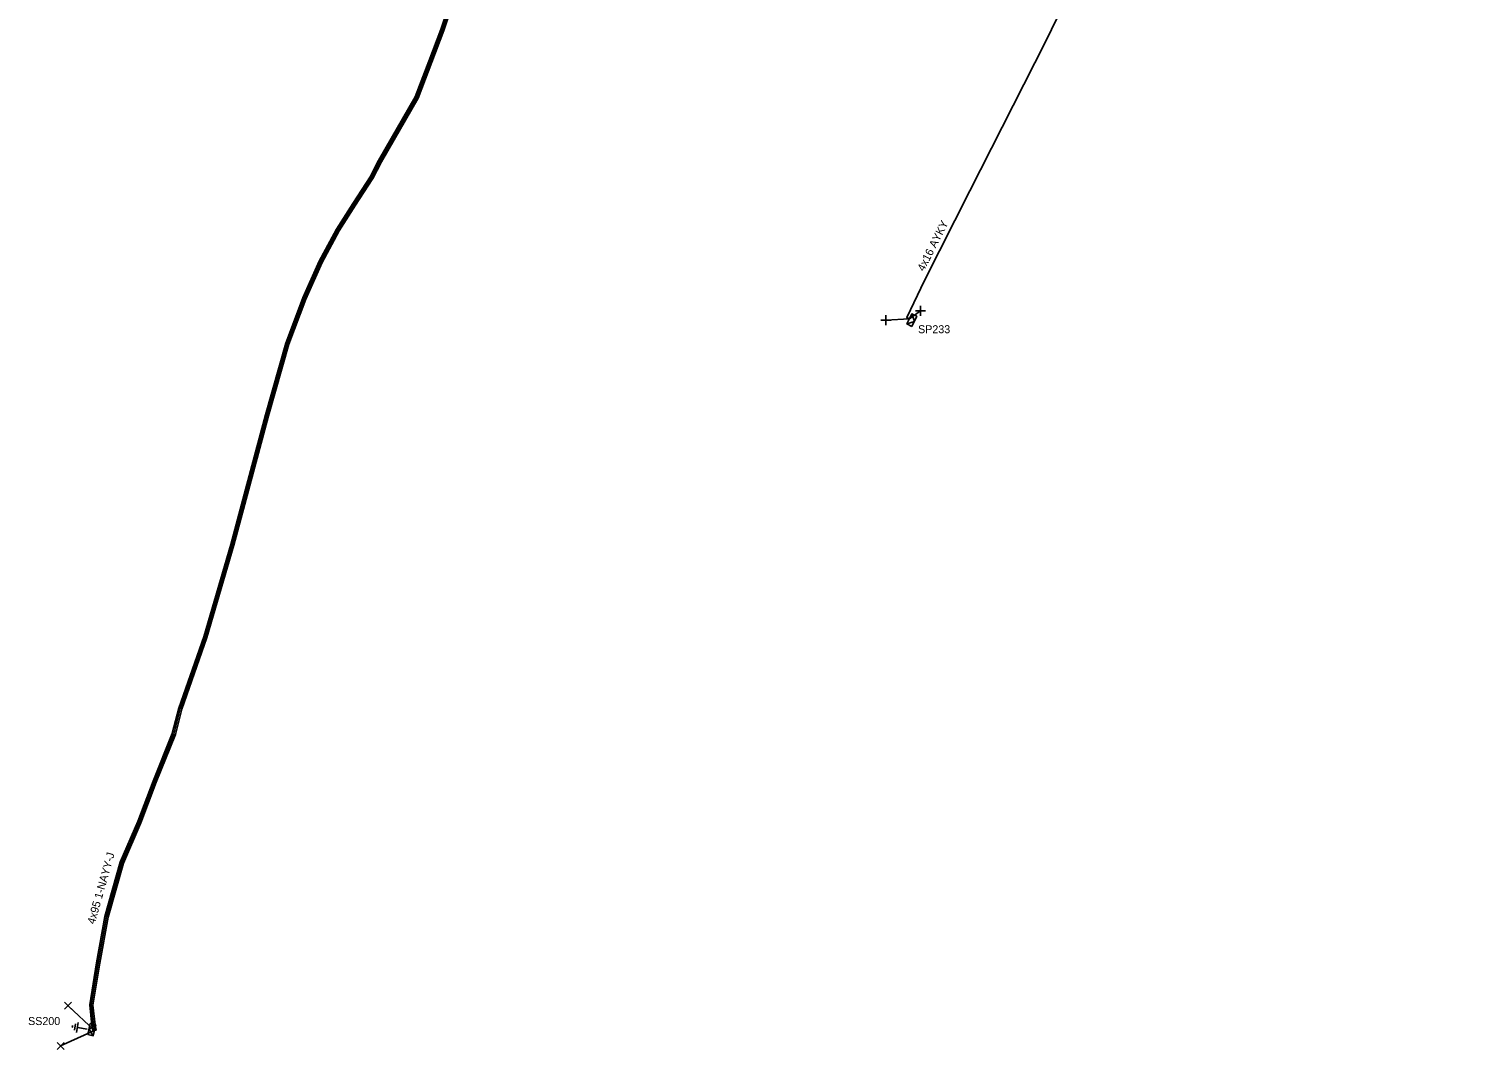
# Model space of a CAD drawing. Extents: x -788458 to -786145, y -1154772 to -1152372.
# Drawn here: x -787453 to -787274.4, y -1153371.6 to -1153244.1 of the extents above; entities that cross this region are included whole.
import ezdxf

# ---------------------------------------------------------------- set-up
doc = ezdxf.new("R2010")
doc.units = 0
for name, color, linetype in [('Vrstva 1', 7, 'Continuous'), ('Vrstva 14', 7, 'Continuous'), ('Vrstva 15', 7, 'Continuous'), ('Vrstva 20', 7, 'Continuous'), ('Vrstva 31', 7, 'Continuous'), ('Vrstva 33', 7, 'Continuous'), ('Vrstva 34', 7, 'Continuous'), ('Vrstva 5', 7, 'Continuous'), ('Vrstva 52', 7, 'Continuous'), ('Vrstva 54', 7, 'Continuous'), ('Vrstva 59', 7, 'Continuous'), ('Vrstva 6', 7, 'Continuous'), ('Vrstva 9', 7, 'Continuous')]:
    doc.layers.add(name, color=color, linetype=linetype)

# ---------------------------------------------------------------- blocks, each defined once
blk = doc.blocks.new('NN800')
at = {"layer": 'Vrstva 1'}
for points in [[(-0.44, 0.44), (0.44, -0.44)], [(-0.44, -0.44), (0.44, 0.44)]]:
    blk.add_lwpolyline(points, dxfattribs=at)
blk = doc.blocks.new('NN630')
at = {"layer": 'Vrstva 9'}
for points in [[(0, -0.7), (-0.7, 0)], [(-0.7, -0.7), (-0.7, 0), (0.7, 0), (0.7, -0.7)], [(-0.7, -0.7), (0.7, -0.7)], [(0, -0.7), (0.7, 0)]]:
    blk.add_lwpolyline(points, dxfattribs=at)
blk = doc.blocks.new('NN810')
at = {"layer": 'Vrstva 14'}
for points in [[(0, -0.64), (0, -1.89)], [(0.63, -1.89), (-0.62, -1.89)], [(0.39, -2.2), (-0.4, -2.2)], [(0, -2.52), (-0.12, -2.52)], [(0.14, -2.52), (0, -2.52)]]:
    blk.add_lwpolyline(points, dxfattribs=at)

msp = doc.modelspace()

# ---------------------------------------------------------------- linework, layer by layer
at = {"layer": 'Vrstva 20'}
msp.add_lwpolyline([(-787400.04, -1153241.2), (-787401.07, -1153244.31), (-787402.59, -1153248.26), (-787404.28, -1153252.75), (-787408.86, -1153260.73), (-787409.95, -1153262.78), (-787412.12, -1153266.12), (-787414.15, -1153269.34), (-787416.29, -1153273.31), (-787418.31, -1153277.88), (-787420.44, -1153283.5), (-787422.97, -1153292.44), (-787425.49, -1153301.77), (-787427.32, -1153308.61), (-787430.68, -1153320.17), (-787433.81, -1153329.12), (-787434.62, -1153332.28), (-787437.02, -1153338.24), (-787438.92, -1153343.29), (-787441.12, -1153348.36), (-787443.03, -1153355.11), (-787444.06, -1153360.85), (-787444.92, -1153366.09), (-787444.65, -1153368.56), (-787444.52, -1153369.2), (-787444.92, -1153369.28), (-787445.05, -1153368.62), (-787445.32, -1153366.07), (-787444.46, -1153360.79), (-787443.43, -1153355.02), (-787441.5, -1153348.22), (-787439.3, -1153343.13), (-787437.4, -1153338.1), (-787435, -1153332.16), (-787434.19, -1153329), (-787431.06, -1153320.05), (-787427.7, -1153308.51), (-787425.87, -1153301.67), (-787423.35, -1153292.34), (-787420.82, -1153283.38), (-787418.69, -1153277.72), (-787416.65, -1153273.13), (-787414.49, -1153269.14), (-787412.46, -1153265.9), (-787410.29, -1153262.58), (-787409.22, -1153260.53), (-787404.64, -1153252.57), (-787402.97, -1153248.12), (-787401.45, -1153244.17), (-787400.42, -1153241.08)], dxfattribs=at)
at = {"layer": 'Vrstva 5'}
msp.add_lwpolyline([(-787400.18, -1153240.99), (-787401.26, -1153244.24), (-787402.78, -1153248.19), (-787404.46, -1153252.66), (-787409.04, -1153260.63), (-787410.12, -1153262.68), (-787412.29, -1153266.01), (-787414.32, -1153269.24), (-787416.47, -1153273.22), (-787418.5, -1153277.8), (-787420.63, -1153283.44), (-787423.16, -1153292.39), (-787425.68, -1153301.72), (-787427.51, -1153308.56), (-787430.87, -1153320.11), (-787434, -1153329.06), (-787434.81, -1153332.22), (-787437.21, -1153338.17), (-787439.11, -1153343.21), (-787441.31, -1153348.29), (-787443.23, -1153355.07), (-787444.26, -1153360.82), (-787445.12, -1153366.08), (-787444.85, -1153368.59), (-787444.72, -1153369.24)], dxfattribs=at)
at = {"layer": 'Vrstva 52'}
msp.add_lwpolyline([(-787274.43, -1153226.44), (-787274.63, -1153225.96), (-787275.64, -1153225.5), (-787282.69, -1153222.25), (-787296.38, -1153233.03), (-787320.74, -1153234.85), (-787321.45, -1153236.52), (-787325.89, -1153245.71), (-787335.36, -1153264.33), (-787341, -1153275.52), (-787343.23, -1153280.17), (-787342.91, -1153280.34)], dxfattribs=at)
at = {"layer": 'Vrstva 59'}
for points in [[(-787342.91, -1153280.34), (-787345.85, -1153280.49)], [(-787342.91, -1153280.34), (-787341.5, -1153279.32)], [(-787444.72, -1153369.24), (-787448.02, -1153366.16)], [(-787444.72, -1153369.24), (-787448.96, -1153371.18)]]:
    msp.add_lwpolyline(points, dxfattribs=at)

# ---------------------------------------------------------------- block references
at = {"layer": 'Vrstva 15', "rotation": -99.79779164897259}
msp.add_blockref('NN810', (-787444.99, -1153369.19), dxfattribs=at)
at = {"layer": 'Vrstva 31'}
for p, rotation in [((-787342.91, -1153280.34), 64.29004623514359), ((-787444.72, -1153369.24), -102.6114299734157)]:
    msp.add_blockref('NN630', p, dxfattribs=dict(at, rotation=rotation))
at = {"layer": 'Vrstva 34', "rotation": 45}
for p in [(-787341.5, -1153279.32), (-787345.85, -1153280.49)]:
    msp.add_blockref('NN800', p, dxfattribs=at)
at = {"layer": 'Vrstva 34'}
for p in [(-787448.02, -1153366.16), (-787448.96, -1153371.18)]:
    msp.add_blockref('NN800', p, dxfattribs=at)

# ---------------------------------------------------------------- texts
at = {"layer": 'Vrstva 33'}
for s, p in [('SP233', (-787341.82, -1153282.13)), ('SS200', (-787453.02, -1153368.58))]:
    msp.add_text(s, height=1, dxfattribs=at).set_placement(p)
at = {"layer": 'Vrstva 54'}
msp.add_text('4x16 AYKY', height=1, rotation=63.217, dxfattribs=at).set_placement((-787341.09, -1153274.47))
at = {"layer": 'Vrstva 6'}
msp.add_text('4x95 1-NAYY-J', height=1, rotation=74.189, dxfattribs=at).set_placement((-787444.7, -1153356.04))

doc.saveas('drawing.dxf')
